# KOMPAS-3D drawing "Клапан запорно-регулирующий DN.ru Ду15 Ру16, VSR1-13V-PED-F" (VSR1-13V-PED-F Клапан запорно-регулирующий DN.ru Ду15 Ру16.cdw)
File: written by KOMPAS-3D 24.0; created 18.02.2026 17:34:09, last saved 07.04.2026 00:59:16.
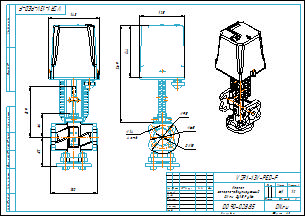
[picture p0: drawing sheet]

Document properties: Автор: R2D2; Форматы листов документа: A3; Полное имя файла: VSR1-13V-PED-F Клапан запорно-регулирующий DN.ru Ду15 Ру16.m3d; Масса: 6.1; Наименование: Клапан запорно-регулирующий DN.ru Ду15 Ру16; Количество листов документа: 1; Примечание: D090-02885

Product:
- Part/product: Клапан запорно-регулирующий DN.ru Ду15 Ру16  | designation VSR1-13V-PED-F
    Масса: 6.1
    Раздел спецификации: Прочие изделия
    Форматы листов документа: A3
    Примечание: D090-02885

Views: Вид 1, Спереди
Referenced files in E:\Работа\Зайцев\Солянка\VSR1-13V-PED-F Клапан запорно-регулирующий DN.ru\DN15\DN15 Kv0.16\: VSR1-13V-PED-F Клапан запорно-регулирующий DN.ru Ду15 Ру16.m3d
Referenced files in E:\Работа\Зайцев\Для компаса\: чертеж DN.ru А3.cdt
Referenced files in E:\Работа\Зайцев\Солянка\VSR1-13V-PED-F Клапан запорно-регулирующий DN.ru\DN15\DN15 Kv1.6\: VSR1-13V-PED-F Клапан запорно-регулирующий DN.ru Ду15 Ру16.m3d
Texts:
  Линейный размер
  VSR1-13V-PED-F
  чертеж DN.ru А3.cdt
  Клапан
  запорно-регулирующий
  DN.ru Ду15 Ру16
  Клапан запорно-регулирующий DN.ru Ду15 Ру16
  VSR1-13V-PED-F Клапан запорно-регулирующий DN.ru Ду15 Ру16
Dimensions and other numbers on the sheet: 0; 3; 2; 4; 130; 82; 143; 64; 139; 1:2; 1; 6,1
